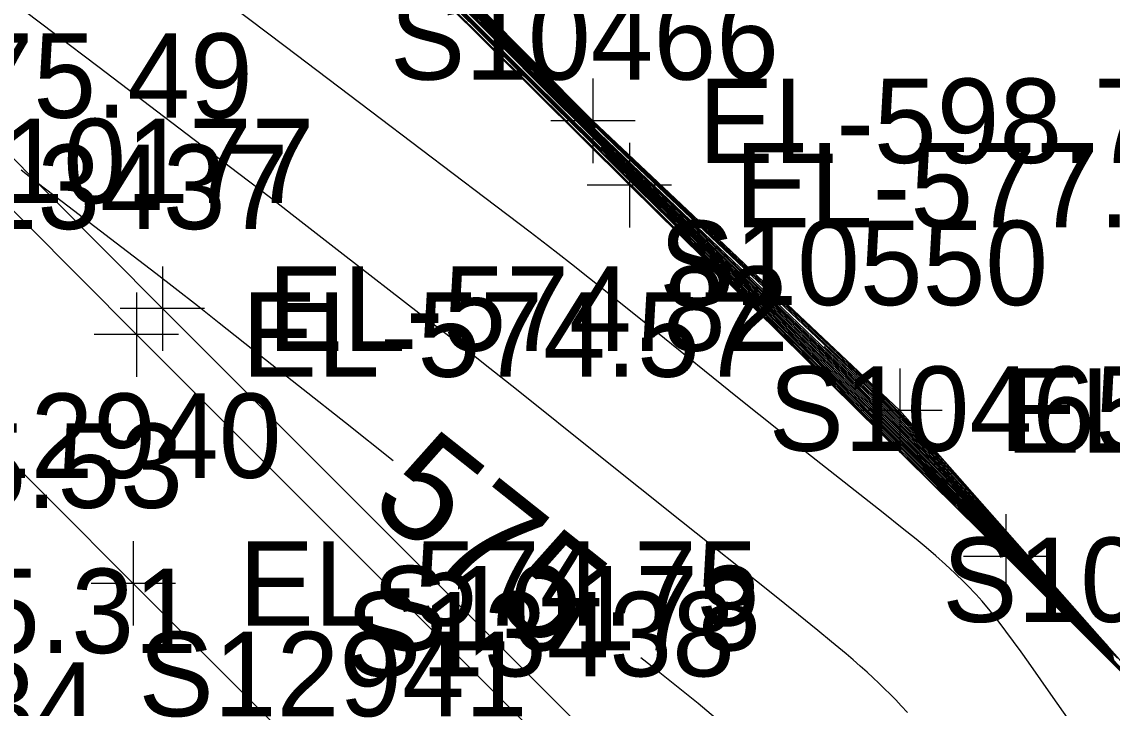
# Model space of a CAD drawing. Extents: x 1729869 to 1735532, y 648588 to 653771.
# Drawn here: x 1730893.8 to 1730945.5, y 652385.1 to 652417.7 of the extents above; entities that cross this region are included whole.
import ezdxf

# ---------------------------------------------------------------- set-up
doc = ezdxf.new("R2010")
doc.units = 0
for name, color, linetype in [('SURVEY - CONTOURS - Index with Text', 7, 'Continuous'), ('SURVEY - CONTOURS - Intermediate with optional Text', 7, 'Continuous'), ('SURVEY - DTM - Breaklines', 7, 'Continuous'), ('SURVEY - DTM - Breaklines - Points - Elevations', 7, 'Continuous'), ('SURVEY - DTM - Breaklines - Points - Locators', 7, 'Continuous'), ('SURVEY - DTM - Breaklines - Points - Numbers', 7, 'Continuous'), ('SURVEY - NON-TRANSPORTATION - Features', 7, 'Continuous'), ('SURVEY - NON-TRANSPORTATION - Features - Points - Elevations', 7, 'Continuous'), ('SURVEY - NON-TRANSPORTATION - Features - Points - Locators', 7, 'Continuous'), ('SURVEY - NON-TRANSPORTATION - Features - Points - Numbers', 7, 'Continuous'), ('SURVEY - TRANSPORTATION - Features', 7, 'Continuous'), ('SURVEY - TRANSPORTATION - Features - Points - Elevations', 7, 'Continuous'), ('SURVEY - TRANSPORTATION - Features - Points - Locators', 7, 'Continuous'), ('SURVEY - TRANSPORTATION - Features - Points - Numbers', 7, 'Continuous'), ('SURVEY - TRANSPORTATION - Roads', 7, 'Continuous'), ('SURVEY - TRANSPORTATION - Roads - Points - Elevations', 7, 'Continuous'), ('SURVEY - TRANSPORTATION - Roads - Points - Locators', 7, 'Continuous'), ('SURVEY - TRANSPORTATION - Roads - Points - Numbers', 7, 'Continuous')]:
    doc.layers.add(name, color=color, linetype=linetype)

msp = doc.modelspace()

# ---------------------------------------------------------------- linework, layer by layer
at = {"layer": 'SURVEY - CONTOURS - Index with Text'}
for points in [[(1730894.023, 652440.825), (1730897.722, 652436.789), (1730902.535, 652431.551), (1730904.528, 652429.39), (1730905.395, 652428.456), (1730905.821, 652428.001), (1730906.584, 652427.194), (1730907.345, 652426.399), (1730908.175, 652425.546), (1730909.022, 652424.682), (1730914.292, 652419.345), (1730918.255, 652415.322), (1730919.473, 652414.093), (1730920.347, 652413.221), (1730920.947, 652412.63)], [(1730945.496, 652387.594), (1730943.212, 652390.071), (1730942.87, 652390.449), (1730942.653, 652390.672), (1730940.211, 652393.289), (1730939.083, 652394.489), (1730937.191, 652396.486), (1730936.601, 652397.103), (1730936.059, 652397.664), (1730935.563, 652398.171), (1730935.07, 652398.669), (1730934.442, 652399.294), (1730933.66, 652400.06), (1730932.753, 652400.938), (1730930.498, 652403.105), (1730928.046, 652405.459), (1730923.976, 652409.376), (1730922.285, 652411.005), (1730921.399, 652411.865), (1730920.614, 652412.635), (1730919.97, 652413.272), (1730919.026, 652414.215), (1730916.765, 652416.492), (1730913.51, 652419.775)], [(1730945.535, 652387.407), (1730944.914, 652388.059), (1730944.569, 652388.409), (1730944.356, 652388.646), (1730943.614, 652389.427), (1730943.374, 652389.683), (1730940.724, 652392.445), (1730939.736, 652393.471), (1730938.418, 652394.827), (1730936.807, 652396.477), (1730936.006, 652397.291), (1730935.353, 652397.947), (1730934.388, 652398.908), (1730933.477, 652399.803), (1730931.895, 652401.343), (1730927.656, 652405.453), (1730924.441, 652408.576), (1730922.016, 652410.936), (1730921.22, 652411.717)], [(1730911.362, 652396.855), (1730909.098, 652398.647), (1730905.094, 652401.813), (1730903.113, 652403.381), (1730902.082, 652404.192), (1730901.021, 652405.02), (1730900.105, 652405.728), (1730898.496, 652406.962), (1730895.673, 652409.117), (1730894.486, 652410.031), (1730893.724, 652410.627)], [(1730946.809, 652385.965), (1730944.015, 652388.809), (1730942.153, 652390.705), (1730940.426, 652392.454), (1730939.091, 652393.795), (1730937.061, 652395.822), (1730935.584, 652397.289), (1730933.848, 652399.004), (1730931.473, 652401.334), (1730924.844, 652407.826), (1730924.727, 652407.941)], [(1730931.799, 652402.275), (1730932.296, 652401.802), (1730933.077, 652401.056), (1730933.842, 652400.32), (1730934.213, 652399.958), (1730934.808, 652399.372), (1730935.265, 652398.913), (1730935.767, 652398.4), (1730936.271, 652397.875), (1730936.617, 652397.51), (1730937.323, 652396.754), (1730938.043, 652395.974), (1730939.371, 652394.525), (1730940.967, 652392.772), (1730942.724, 652390.831), (1730944.155, 652389.241), (1730945.534, 652387.704), (1730945.602, 652387.635), (1730947.199, 652385.84), (1730948.064, 652384.874), (1730948.165, 652384.764), (1730948.175, 652384.754)], [(1730926.646, 652384.664), (1730925.814, 652385.345), (1730924.719, 652386.232), (1730923.609, 652387.122), (1730923.106, 652387.523)]]:
    msp.add_lwpolyline(points, dxfattribs=at)
at = {"layer": 'SURVEY - CONTOURS - Intermediate with optional Text'}
for points in [[(1730945.917, 652386.925), (1730944.821, 652388.055), (1730944.44, 652388.446), (1730943.664, 652389.251), (1730942.161, 652390.798), (1730940.247, 652392.756), (1730939.081, 652393.942), (1730936.96, 652396.081), (1730935.995, 652397.049), (1730934.854, 652398.185), (1730933.74, 652399.284), (1730932.265, 652400.729), (1730925.2, 652407.621), (1730922.059, 652410.695), (1730920.724, 652412.01), (1730919.127, 652413.593), (1730915.095, 652417.613), (1730909.382, 652423.302)], [(1730910.547, 652423.301), (1730918.145, 652415.564), (1730919.066, 652414.632), (1730919.976, 652413.719), (1730920.725, 652412.977), (1730921.389, 652412.329), (1730921.832, 652411.9), (1730922.728, 652411.041), (1730924.574, 652409.288), (1730929.467, 652404.651), (1730932.182, 652402.083), (1730933.051, 652401.255), (1730933.48, 652400.845), (1730933.901, 652400.438), (1730934.314, 652400.036), (1730934.845, 652399.511), (1730935.356, 652398.995), (1730935.743, 652398.598), (1730936.267, 652398.05), (1730936.656, 652397.635), (1730937.053, 652397.208), (1730937.456, 652396.771), (1730938.271, 652395.876), (1730939.726, 652394.266), (1730942.133, 652391.586), (1730942.393, 652391.296)], [(1730947.414, 652385.332), (1730943.984, 652388.802), (1730942.148, 652390.66), (1730940.413, 652392.406), (1730939.103, 652393.716), (1730937.008, 652395.796), (1730935.122, 652397.662), (1730932.805, 652399.942), (1730924.415, 652408.176), (1730922.059, 652410.495), (1730919.768, 652412.762), (1730910.147, 652422.31)], [(1730946.334, 652386.471), (1730944.208, 652388.649), (1730942.937, 652389.954), (1730940.982, 652391.948), (1730939.89, 652393.057), (1730938.678, 652394.278), (1730936.579, 652396.383), (1730935.194, 652397.761), (1730933.785, 652399.153), (1730931.89, 652401.01), (1730925.236, 652407.514), (1730922.251, 652410.44), (1730920.709, 652411.96), (1730918.933, 652413.722), (1730911.001, 652421.616)], [(1730945.892, 652386.978), (1730944.855, 652388.054), (1730944.475, 652388.441), (1730944.285, 652388.644), (1730943.434, 652389.531), (1730941.812, 652391.208), (1730940.023, 652393.047), (1730939.079, 652394.012), (1730936.777, 652396.345), (1730935.995, 652397.133), (1730934.913, 652398.213), (1730933.805, 652399.307), (1730932.604, 652400.483), (1730929.777, 652403.236), (1730924.795, 652408.088), (1730921.835, 652410.982), (1730920.741, 652412.058), (1730919.36, 652413.427), (1730916.496, 652416.283), (1730912.386, 652420.386)], [(1730943.34, 652384.667), (1730942.656, 652385.637), (1730941.477, 652387.314), (1730941.13, 652387.803), (1730940.776, 652388.294), (1730940.416, 652388.783), (1730940.047, 652389.265), (1730939.668, 652389.739), (1730939.279, 652390.2), (1730939.142, 652390.355), (1730939.003, 652390.509), (1730938.863, 652390.661), (1730938.721, 652390.812), (1730938.577, 652390.961), (1730938.431, 652391.109), (1730937.998, 652391.531), (1730937.55, 652391.945), (1730937.091, 652392.35), (1730936.625, 652392.747), (1730936.154, 652393.137), (1730935.501, 652393.665), (1730934.595, 652394.385), (1730931.196, 652397.062), (1730929.705, 652398.247), (1730927.691, 652399.859), (1730923.817, 652402.974), (1730921.907, 652404.509), (1730920.667, 652405.498), (1730919.822, 652406.165), (1730919.165, 652406.678), (1730918.674, 652407.058), (1730917.86, 652407.68), (1730915.705, 652409.312), (1730912.698, 652411.591), (1730910.284, 652413.427), (1730906.248, 652416.477), (1730901.856, 652419.794)], [(1730945.872, 652387.027), (1730944.886, 652388.055), (1730944.519, 652388.428), (1730944.322, 652388.644), (1730943.63, 652389.369), (1730943.409, 652389.603), (1730943.163, 652389.856), (1730941.832, 652391.239), (1730940.003, 652393.131), (1730939.078, 652394.081), (1730936.792, 652396.412), (1730935.999, 652397.213), (1730934.971, 652398.242), (1730933.94, 652399.262), (1730932.796, 652400.381), (1730930.251, 652402.856), (1730927.267, 652405.755), (1730924.43, 652408.516), (1730921.804, 652411.077), (1730920.759, 652412.105), (1730919.627, 652413.226), (1730917.593, 652415.255), (1730913.019, 652419.828)], [(1730945.528, 652387.443), (1730944.941, 652388.064), (1730944.627, 652388.383), (1730944.385, 652388.652), (1730943.599, 652389.485), (1730943.078, 652390.039), (1730942.773, 652390.357), (1730941.569, 652391.619), (1730941.262, 652391.937), (1730941.008, 652392.207), (1730939.705, 652393.568), (1730938.452, 652394.865), (1730936.824, 652396.542), (1730936.015, 652397.367), (1730935.395, 652397.993), (1730934.78, 652398.606), (1730933.995, 652399.382), (1730933.026, 652400.329), (1730930.926, 652402.365), (1730928.014, 652405.183), (1730924.452, 652408.635), (1730922.007, 652411.011), (1730921.116, 652411.883), (1730920.158, 652412.828), (1730918.98, 652414), (1730916.031, 652416.955), (1730913.099, 652419.895)], [(1730945.521, 652387.479), (1730944.967, 652388.069), (1730944.684, 652388.361), (1730944.413, 652388.659), (1730943.306, 652389.84), (1730943.031, 652390.137), (1730942.743, 652390.435), (1730941.603, 652391.637), (1730941.316, 652391.937), (1730940.771, 652392.513), (1730939.674, 652393.665), (1730938.485, 652394.903), (1730938.189, 652395.21), (1730937.89, 652395.517), (1730937.629, 652395.79), (1730936.58, 652396.874), (1730936.025, 652397.442), (1730935.437, 652398.037), (1730934.853, 652398.622), (1730934.059, 652399.408), (1730933.293, 652400.156), (1730931.592, 652401.804), (1730928.022, 652405.252), (1730924.465, 652408.694), (1730921.998, 652411.086), (1730921.121, 652411.942), (1730920.207, 652412.844), (1730919.261, 652413.784), (1730916.96, 652416.091), (1730913.444, 652419.623)], [(1730945.513, 652387.517), (1730944.992, 652388.075), (1730944.735, 652388.344), (1730944.441, 652388.666), (1730943.275, 652389.915), (1730942.98, 652390.239), (1730942.714, 652390.513), (1730940.219, 652393.155), (1730939.363, 652394.057), (1730938.237, 652395.233), (1730937.956, 652395.524), (1730937.406, 652396.1), (1730936.587, 652396.951), (1730936.036, 652397.517), (1730935.479, 652398.082), (1730934.926, 652398.637), (1730934.21, 652399.346), (1730933.586, 652399.957), (1730932.489, 652401.022), (1730930.125, 652403.302), (1730927.725, 652405.616), (1730924.184, 652409.036), (1730921.99, 652411.159), (1730921.127, 652412.002), (1730920.255, 652412.86), (1730919.288, 652413.823), (1730917.274, 652415.843), (1730913.466, 652419.673)], [(1730945.505, 652387.555), (1730944.776, 652388.338), (1730943.857, 652389.333), (1730943.244, 652389.992), (1730942.926, 652390.344), (1730942.684, 652390.592), (1730940.215, 652393.222), (1730939.348, 652394.14), (1730937.447, 652396.137), (1730936.594, 652397.027), (1730936.047, 652397.591), (1730935.521, 652398.127), (1730934.998, 652398.653), (1730934.278, 652399.368), (1730933.623, 652400.008), (1730932.467, 652401.128), (1730930.15, 652403.358), (1730927.747, 652405.67), (1730924.212, 652409.079), (1730921.982, 652411.233), (1730921.132, 652412.061), (1730920.303, 652412.877), (1730919.315, 652413.861), (1730917.559, 652415.624), (1730913.488, 652419.724)], [(1730945.485, 652387.634), (1730943.514, 652389.785), (1730943.178, 652390.151), (1730942.823, 652390.542), (1730942.621, 652390.754), (1730940.206, 652393.356), (1730939.084, 652394.558), (1730937.529, 652396.209), (1730936.913, 652396.86), (1730936.306, 652397.495), (1730935.838, 652397.978), (1730935.374, 652398.451), (1730934.713, 652399.114), (1730934.314, 652399.508), (1730933.697, 652400.111), (1730932.744, 652401.032), (1730930.539, 652403.147), (1730928.055, 652405.528), (1730922.619, 652410.749), (1730921.638, 652411.697), (1730920.895, 652412.423), (1730920.028, 652413.279), (1730919.036, 652414.27), (1730917.05, 652416.272), (1730913.533, 652419.824)], [(1730945.473, 652387.676), (1730943.495, 652389.848), (1730942.782, 652390.628), (1730940.201, 652393.425), (1730939.084, 652394.627), (1730937.571, 652396.245), (1730936.931, 652396.924), (1730936.302, 652397.584), (1730935.865, 652398.037), (1730935.431, 652398.48), (1730934.793, 652399.122), (1730934.378, 652399.533), (1730933.734, 652400.162), (1730932.734, 652401.127), (1730930.581, 652403.188), (1730928.064, 652405.596), (1730922.64, 652410.795), (1730921.612, 652411.787), (1730920.914, 652412.469), (1730920.086, 652413.286), (1730919.046, 652414.325), (1730917.074, 652416.317), (1730913.557, 652419.873)], [(1730913.796, 652419.776), (1730918.291, 652415.219), (1730919.447, 652414.053), (1730920.349, 652413.154), (1730921.149, 652412.368), (1730921.924, 652411.616), (1730923.059, 652410.526), (1730929.501, 652404.38), (1730932.333, 652401.682), (1730933.444, 652400.617), (1730934.162, 652399.921), (1730934.734, 652399.357), (1730935.175, 652398.915), (1730935.731, 652398.349), (1730936.291, 652397.768), (1730936.626, 652397.415), (1730937.31, 652396.685), (1730938.537, 652395.361), (1730939.815, 652393.972), (1730941.312, 652392.334), (1730942.669, 652390.843), (1730943.839, 652389.548), (1730945.436, 652387.771), (1730945.706, 652387.5)], [(1730913.996, 652419.502), (1730918.321, 652415.122), (1730919.421, 652414.014), (1730920.281, 652413.157), (1730920.932, 652412.515), (1730921.583, 652411.88), (1730922.661, 652410.842), (1730928.765, 652405.002), (1730932.366, 652401.565), (1730933.425, 652400.549), (1730934.111, 652399.883), (1730934.66, 652399.342), (1730935.086, 652398.918), (1730935.69, 652398.304), (1730936.298, 652397.675), (1730936.949, 652396.988), (1730937.614, 652396.279), (1730939.284, 652394.481), (1730940.552, 652393.106), (1730942.549, 652390.928), (1730943.844, 652389.504), (1730945.457, 652387.721)], [(1730915.122, 652418.571), (1730918.209, 652415.434), (1730919.068, 652414.565), (1730919.921, 652413.709), (1730920.659, 652412.977), (1730921.297, 652412.353), (1730921.873, 652411.795), (1730922.714, 652410.988), (1730925.476, 652408.362), (1730929.914, 652404.147), (1730932.66, 652401.542), (1730933.475, 652400.762), (1730933.873, 652400.378), (1730934.262, 652399.998), (1730934.764, 652399.504), (1730935.244, 652399.022), (1730935.661, 652398.597), (1730936.11, 652398.131), (1730936.623, 652397.588), (1730936.992, 652397.193), (1730937.746, 652396.376), (1730939.06, 652394.934), (1730940.586, 652393.25), (1730942.525, 652391.099), (1730945.279, 652388.03)], [(1730935.747, 652384.922), (1730935.449, 652385.246), (1730935.19, 652385.518), (1730934.926, 652385.787), (1730934.659, 652386.052), (1730934.388, 652386.314), (1730934.113, 652386.573), (1730933.833, 652386.829), (1730933.504, 652387.124), (1730933.17, 652387.416), (1730932.833, 652387.706), (1730932.493, 652387.993), (1730932.15, 652388.278), (1730931.501, 652388.81), (1730930.584, 652389.553), (1730929.288, 652390.59), (1730925.028, 652393.981), (1730921.113, 652397.108), (1730917.212, 652400.226), (1730915.947, 652401.231), (1730914.938, 652402.027), (1730914.066, 652402.707), (1730912.584, 652403.854), (1730908.994, 652406.632), (1730906.574, 652408.511), (1730905.539, 652409.309), (1730904.046, 652410.45), (1730897.357, 652415.533), (1730895.345, 652417.056), (1730893.86, 652418.173)], [(1730946.123, 652386.612), (1730944.598, 652388.141), (1730941.649, 652391.106), (1730940.127, 652392.629), (1730938.622, 652394.124), (1730936.607, 652396.115), (1730932.961, 652399.704), (1730923.926, 652408.582), (1730922.215, 652410.271), (1730921.18, 652411.299), (1730920.137, 652412.341), (1730919.041, 652413.447), (1730918.313, 652414.188), (1730917.812, 652414.689), (1730915.656, 652416.826), (1730915.061, 652417.419), (1730914.863, 652417.613), (1730914.623, 652417.829)], [(1730916.418, 652417.401), (1730917.741, 652416.045), (1730918.59, 652415.181), (1730919.512, 652414.251), (1730919.989, 652413.773), (1730920.748, 652413.022), (1730921.215, 652412.566), (1730921.703, 652412.092), (1730922.196, 652411.618), (1730923.188, 652410.671), (1730925.839, 652408.16), (1730932.108, 652402.236), (1730933.048, 652401.342), (1730933.51, 652400.9), (1730933.963, 652400.462), (1730934.405, 652400.03), (1730934.973, 652399.466), (1730935.383, 652399.051), (1730935.853, 652398.566), (1730936.256, 652398.143), (1730936.656, 652397.717), (1730937.054, 652397.288), (1730937.446, 652396.86), (1730938.196, 652396.031), (1730939.132, 652394.984), (1730939.507, 652394.563)], [(1730926.162, 652407.933), (1730931.063, 652403.299), (1730932.486, 652401.948), (1730933.501, 652400.979), (1730933.976, 652400.521), (1730934.422, 652400.087), (1730934.962, 652399.554), (1730935.435, 652399.078), (1730935.767, 652398.736), (1730936.208, 652398.271), (1730936.621, 652397.829)]]:
    msp.add_lwpolyline(points, dxfattribs=at)
at = {"layer": 'SURVEY - DTM - Breaklines'}
for points in [[(1730587.774, 652756.33), (1730594.925, 652741.91), (1730609.577, 652716.644), (1730625.689, 652692.371), (1730643.455, 652668.78), (1730662.354, 652646.079), (1730682.257, 652624.222), (1730702.707, 652602.668), (1730723.576, 652581.257), (1730744.651, 652559.957), (1730765.85, 652538.806), (1730769.397, 652535.272), (1730794.44, 652510.116), (1730815.612, 652488.907), (1730836.832, 652467.723), (1730858.033, 652446.55), (1730879.263, 652425.34), (1730900.421, 652404.063), (1730921.638, 652382.868), (1730942.829, 652361.634), (1730964.104, 652340.505), (1730985.371, 652319.345), (1731006.623, 652298.196)], [(1731173.177, 652162.133), (1731170.5, 652159.498), (1731153.304, 652177.685), (1731135.911, 652195.641), (1731118.174, 652213.343), (1731103.282, 652228.587), (1731085.963, 652246.682), (1731068.193, 652264.268), (1731049.977, 652281.46), (1731042.311, 652290.419), (1731041.406, 652292.943), (1731038.991, 652294.926), (1731037.062, 652296.182), (1731033.469, 652298.672), (1731021.7, 652310.15), (1731004.316, 652328.046), (1730986.687, 652345.773), (1730968.734, 652363.274), (1730957.995, 652374.725), (1730940.405, 652392.322), (1730922.559, 652409.914), (1730904.882, 652427.475), (1730887.191, 652445.181), (1730869.266, 652462.674)]]:
    msp.add_lwpolyline(points, dxfattribs=at)
at = {"layer": 'SURVEY - DTM - Breaklines - Points - Locators'}
for p, q in [((1730922.559, 652411.914), (1730922.559, 652407.914)), ((1730924.559, 652409.914), (1730920.559, 652409.914)), ((1730900.421, 652406.063), (1730900.421, 652402.063)), ((1730902.421, 652404.063), (1730898.421, 652404.063)), ((1730940.405, 652394.322), (1730940.405, 652390.322)), ((1730942.405, 652392.322), (1730938.405, 652392.322))]:
    msp.add_line(p, q, dxfattribs=at)
at = {"layer": 'SURVEY - NON-TRANSPORTATION - Features'}
msp.add_lwpolyline([(1731129.077, 652202.89), (1731120.396, 652211.708), (1731120.19, 652212.027), (1731106.2, 652226.321), (1731096.433, 652236.798), (1731082.025, 652250.676), (1731067.826, 652264.761), (1731054.94, 652277.741), (1731041.956, 652294.13), (1731033.801, 652299.661), (1731019.009, 652313.155), (1731005.147, 652327.576), (1730991.058, 652341.771), (1730976.781, 652355.779), (1730962.739, 652370.02), (1730948.65, 652384.215), (1730935.383, 652399.23), (1730920.832, 652412.964), (1730906.726, 652427.142), (1730893.11, 652441.809), (1730878.159, 652455.144), (1730863.664, 652468.934)], dxfattribs=at)
at = {"layer": 'SURVEY - NON-TRANSPORTATION - Features - Points - Locators'}
for p, q in [((1730920.832, 652414.964), (1730920.832, 652410.964)), ((1730922.832, 652412.964), (1730918.832, 652412.964)), ((1730935.383, 652401.23), (1730935.383, 652397.23)), ((1730937.383, 652399.23), (1730933.383, 652399.23))]:
    msp.add_line(p, q, dxfattribs=at)
at = {"layer": 'SURVEY - TRANSPORTATION - Features'}
msp.add_lwpolyline([(1730835.6, 652466.493), (1730856.805, 652445.317), (1730878.032, 652424.109), (1730899.189, 652402.834), (1730920.407, 652381.638), (1730941.598, 652360.404), (1730962.875, 652339.272), (1730984.142, 652318.113), (1731005.396, 652296.96), (1731008.075, 652296.352)], dxfattribs=at)
at = {"layer": 'SURVEY - TRANSPORTATION - Features - Points - Locators'}
for p, q in [((1730899.189, 652404.834), (1730899.189, 652400.834)), ((1730901.189, 652402.834), (1730897.189, 652402.834))]:
    msp.add_line(p, q, dxfattribs=at)
at = {"layer": 'SURVEY - TRANSPORTATION - Roads'}
msp.add_lwpolyline([(1730831.15, 652458.88), (1730843.882, 652446.168), (1730863.714, 652426.414), (1730875.025, 652415.105), (1730899.039, 652391.043), (1730910.369, 652379.748), (1730935.764, 652354.333), (1730956.03, 652334.21), (1730971.982, 652318.295), (1730987.466, 652302.848), (1731007.326, 652283.108), (1731032.831, 652257.697), (1731045.572, 652244.982), (1731076.702, 652213.886), (1731092.244, 652198.318)], dxfattribs=at)
at = {"layer": 'SURVEY - TRANSPORTATION - Roads - Points - Locators'}
for p, q in [((1730899.039, 652393.043), (1730899.039, 652389.043)), ((1730901.039, 652391.043), (1730897.039, 652391.043))]:
    msp.add_line(p, q, dxfattribs=at)

# ---------------------------------------------------------------- texts
at = {"layer": 'SURVEY - CONTOURS - Index with Text'}
msp.add_text('575', height=5, rotation=321.5272, dxfattribs=at).set_placement((1730910.101, 652394.667))
at = {"layer": 'SURVEY - DTM - Breaklines - Points - Elevations'}
for s, p in [('EL-577.74', (1730927.559, 652407.914)), ('EL-574.82', (1730905.421, 652402.063))]:
    msp.add_text(s, height=4, dxfattribs=at).set_placement(p)
at = {"layer": 'SURVEY - DTM - Breaklines - Points - Numbers'}
for s, p in [('S10466', (1730911.209, 652414.914)), ('S10177', (1730889.181, 652409.063)), ('S10465', (1730929.165, 652397.322)), ('S10178', (1730910.351, 652387.868))]:
    msp.add_text(s, height=4, dxfattribs=at).set_placement(p)
at = {"layer": 'SURVEY - NON-TRANSPORTATION - Features - Points - Elevations'}
for s, p in [('EL-598.75', (1730925.832, 652410.964)), ('EL-599.43', (1730940.383, 652397.23))]:
    msp.add_text(s, height=4, dxfattribs=at).set_placement(p)
at = {"layer": 'SURVEY - NON-TRANSPORTATION - Features - Points - Numbers'}
for s, p in [('S10550', (1730923.97, 652404.23)), ('S10549', (1730937.395, 652389.215))]:
    msp.add_text(s, height=4, dxfattribs=at).set_placement(p)
at = {"layer": 'SURVEY - TRANSPORTATION - Features - Points - Elevations'}
for s, p in [('EL-574.57', (1730904.189, 652400.834)), ('EL-575.31', (1730877.363, 652387.742))]:
    msp.add_text(s, height=4, dxfattribs=at).set_placement(p)
at = {"layer": 'SURVEY - TRANSPORTATION - Features - Points - Numbers'}
for s, p in [('S13437', (1730887.949, 652407.834)), ('S13438', (1730909.12, 652386.638))]:
    msp.add_text(s, height=4, dxfattribs=at).set_placement(p)
at = {"layer": 'SURVEY - TRANSPORTATION - Roads - Points - Elevations'}
for s, p in [('EL-575.49', (1730880.025, 652413.105)), ('EL-575.53', (1730876.708, 652394.621)), ('EL-574.75', (1730904.039, 652389.043))]:
    msp.add_text(s, height=4, dxfattribs=at).set_placement(p)
at = {"layer": 'SURVEY - TRANSPORTATION - Roads - Points - Numbers'}
for s, p in [('S12940', (1730887.626, 652396.043)), ('S12941', (1730899.287, 652384.748)), ('S13134', (1730878.913, 652383.304))]:
    msp.add_text(s, height=4, dxfattribs=at).set_placement(p)

doc.saveas('drawing.dxf')
